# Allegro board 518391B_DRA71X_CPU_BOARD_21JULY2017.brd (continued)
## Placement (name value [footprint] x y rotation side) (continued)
R249  4.7k  [R402-25]  148.84 84.2 270 bottom
R250  1K  [R402-25]  140.97 83.44 180 bottom
R251  10K  [R402-25]  134.75 83.44 180 bottom
R252  0  [R402-25]  42.16 85.47 0 bottom
R253  0  [R402-25]  37.97 85.47 0 bottom
R254  1K  [R402-25]  140.97 81.53 180 bottom
R255  10K  [R402-25]  134.75 81.41 180 bottom
R256  0  [R402-25]  42.16 83.69 0 bottom
R257  0  [R402-25]  37.97 83.69 0 bottom
R258  1K  [R402-25]  140.97 79.5 180 bottom
R259  10K  [R402-25]  134.75 79.5 180 bottom
R261  0  [R402-25]  37.97 81.91 0 bottom
R262  10K  [R402-25]  72.52 77.22 180 bottom
R263  100  [R402-25]  74.3 76.71 270 bottom
R264  22  [R402-25]  76.96 76.33 180 bottom
R265  0  [R201-6P6SPC]  77.85 74.8 0 bottom
R266  0  [R201-6P6SPC]  77.85 73.91 0 bottom
R267  0  [R201-6P6SPC]  79.38 72.52 0 bottom
R268  47K  [R402-25]  129.16 63.88 90 bottom
R269  47K  [R402-25]  122.05 64.9 270 bottom
R270  47K  [R402-25]  129.16 61.85 270 bottom
R271  47K  [R402-25]  119.38 61.98 270 bottom
R272  47K  [R402-25]  126.36 64.77 270 bottom
R273  47K  [R402-25]  119.38 64.9 270 bottom
R274  NP  [R402-25]  145.29 71.37 270 bottom
R275  40.2K  [R402-25]  144.14 71.37 90 bottom
R276  49.9  [SM-7351-RES-0402]  62.36 71.25 90 bottom
R277  49.9  [SM-7351-RES-0402]  61.21 71.25 90 bottom
R278  49.9  [SM-7351-RES-0402]  60.07 71.25 90 bottom
R279  49.9  [SM-7351-RES-0402]  58.93 71.25 90 bottom
R280  49.9  [SM-7351-RES-0402]  57.78 71.25 90 bottom
R281  49.9  [SM-7351-RES-0402]  56.64 71.25 90 bottom
R282  49.9  [SM-7351-RES-0402]  55.5 71.25 90 bottom
R283  49.9  [SM-7351-RES-0402]  54.36 71.25 90 bottom
R284  49.9  [SM-7351-RES-0402]  53.21 71.25 90 bottom
R285  49.9  [SM-7351-RES-0402]  52.07 71.25 90 bottom
R286  49.9  [SM-7351-RES-0402]  50.93 71.25 90 bottom
R287  49.9  [SM-7351-RES-0402]  49.78 71.25 90 bottom
R288  49.9  [SM-7351-RES-0402]  48.64 71.25 90 bottom
R289  47K  [R402-25]  126.36 62.1 270 bottom
R290  10K  [R402-25]  148.08 68.96 180 bottom
R291  47K  [R402-25]  122.05 60.96 90 bottom
R292  22  [R402-25]  98.93 67.06 270 bottom
R293  680  [R402-25]  10.03 63.63 90 bottom
R294  NP-0  [R402-25]  8.76 63.63 90 bottom
R295  47K  [R402-25]  124.08 60.96 270 bottom
R296  1K  [R402-25]  123.44 63.63 90 bottom
R297  NP  [R402-25]  141.48 63.25 270 bottom
R298  40.2K  [R402-25]  140.34 63.25 90 bottom
R299  0  [R402-25]  124.71 59.56 0 bottom
R300  NP  [R402-25]  124.71 58.55 180 bottom
R301  NP-75  [R402-25]  12.57 62.36 90 bottom
R302  NP-75  [R402-25]  15.11 61.09 90 bottom
R303  49.9  [SM-7351-RES-0402]  80.14 60.71 90 bottom
R304  680  [R402-25]  12.57 59.82 90 bottom
R305  0  [R201-6P6SPC]  151.38 58.42 270 bottom
R306  10K  [R402-25]  153.54 57.91 270 bottom
R307  4.7K  [R402-25]  121.92 53.97 90 bottom
R308  100  [R402-25]  127 54.61 270 top
R309  0  [R402-25]  119.38 54.48 90 bottom
R310  4.7K  [R402-25]  118.11 54.48 90 bottom
R311  4.7K  [R402-25]  116.97 54.48 90 bottom
R312  4.7K  [R402-25]  120.65 53.97 270 bottom
R313  10K  [R402-25]  33.53 52.7 180 bottom
R314  680  [R402-25]  10.03 52.2 90 bottom
R315  NP-0  [R402-25]  8.76 52.2 90 bottom
R316  100  [R402-25]  133.22 51.82 90 bottom
R317  100  [R402-25]  132.21 51.82 90 bottom
R318  NP-75  [R402-25]  12.57 50.93 90 bottom
R319  10K  [R402-25]  140.46 49.91 270 bottom
R320  10K  [R402-25]  33.66 49.78 180 bottom
R321  NP-75  [R402-25]  15.11 49.66 90 bottom
R322  10K  [R402-25]  132.97 48.89 0 bottom
R323  1K  [R402-25]  130.81 48.89 0 bottom
R324  100  [R402-25]  41.66 48.39 180 bottom
R325  200  [R402-25]  39.5 48.39 180 bottom
R326  680  [R402-25]  12.57 48.39 90 bottom
R327  100  [R402-25]  128.27 48.13 0 bottom
R328  4.7K  [R402-25]  122.56 48.13 270 bottom
R329  4.7K  [R402-25]  121.28 48.13 270 bottom
R330  4.7K  [R402-25]  120.14 48.13 270 bottom
R331  100  [R402-25]  128.27 47.12 0 bottom
R332  100K  [R402-25]  139.7 46.86 180 bottom
R333  10K  [R402-25]  22.23 46.74 270 bottom
R334  10K  [R402-25]  150.88 46.23 90 bottom
R335  100  [R402-25]  128.27 46.1 0 bottom
R336  100  [R402-25]  158.5 45.97 180 bottom
R337  NP  [R402-25]  156.97 45.47 270 bottom
R338  10K  [R402-25]  155.83 45.47 90 bottom
R339  NP  [R402-25]  154.69 45.47 90 bottom
R340  10K  [R402-25]  153.54 45.47 270 bottom
R341  100  [R402-25]  128.27 45.08 0 bottom
R342  10K  [R402-25]  116.46 44.7 180 bottom
R343  0  [R402-25]  100.08 44.7 180 bottom
R344  1.5K  [R402-25]  119.13 44.58 270 bottom
R345  4.7K  [R402-25]  135.89 44.45 90 bottom
R346  240  [R402-25]  116.46 43.69 180 bottom
R347  10K  [R402-25]  106.81 43.43 180 bottom
R348  10K  [R402-25]  139.83 43.31 0 bottom
R349  100  [R402-25]  135.89 42.29 270 bottom
R350  4.7K  [R402-25]  106.81 42.16 0 bottom
R351  4.7K  [R402-25]  106.81 40.89 0 bottom
R352  680  [R402-25]  10.03 40.77 90 bottom
R353  NP-0  [R402-25]  8.76 40.77 90 bottom
R354  10K  [R402-25]  138.18 40.39 270 bottom
R355  10K  [R402-25]  136.78 40.39 90 bottom
R356  100  [R402-25]  132.72 40.39 90 bottom
R357  100  [R402-25]  131.57 40.39 90 bottom
R358  10K  [R402-25]  117.98 39.75 0 bottom
R359  NP-75  [R402-25]  12.57 39.5 90 bottom
R360  10K  [R402-25]  117.98 38.61 0 bottom
R361  NP-75  [R402-25]  15.11 38.23 90 bottom
R362  0  [R402-25]  158.24 37.97 0 bottom
R363  63.4K  [R402-25]  155.96 37.97 0 bottom
R364  63.4K  [R402-25]  153.8 37.97 0 bottom
R365  10K  [R402-25]  117.98 37.46 0 bottom
R366  680  [R402-25]  12.57 36.96 90 bottom
R367  0  [R402-25]  158.24 36.83 0 bottom
R368  10K  [R402-25]  155.96 36.83 180 bottom
R369  10K  [R402-25]  153.8 36.83 180 bottom
R370  10K  [R402-25]  87.63 40.51 270 bottom
R371  100  [R402-25]  129.03 35.56 270 bottom
R372  100  [R402-25]  127.89 35.56 270 bottom
R373  47K  [R402-25]  86.61 39.75 270 bottom
R374  10K  [R402-25]  113.54 34.42 90 bottom
R375  10K  [R402-25]  112.27 34.42 270 bottom
R376  100  [R402-25]  109.73 34.42 90 bottom
R377  NP  [R402-25]  101.47 34.04 90 bottom
R378  10K  [R402-25]  84.2 39.24 0 bottom
R379  1.5K  [R402-25]  156.97 31.37 90 bottom
R380  1.5K  [R402-25]  155.7 31.37 90 bottom
R381  10K  [R402-25]  158.62 30.86 0 bottom
R382  10K  [R402-25]  136.27 29.84 90 bottom
R383  10K  [R402-25]  128.65 29.84 270 bottom
R384  10K  [R402-25]  158.62 29.72 0 bottom
R385  680  [R402-25]  10.03 29.34 90 bottom
R386  NP-0  [R402-25]  8.76 29.34 90 bottom
R387  NP-75  [R402-25]  12.57 28.07 90 bottom
R388  62  [R1206-40X70]  133.48 27.05 180 bottom
R389  62  [R1206-40X70]  124.59 27.05 0 bottom
R390  NP-75  [R402-25]  15.11 26.8 90 bottom
R391  NP  [R402-25]  101.47 26.42 90 bottom
R392  680  [R402-25]  12.57 25.53 90 bottom
R393  NP  [R402-25]  133.35 25.27 0 bottom
R394  NP  [R402-25]  130.18 25.15 180 bottom
R395  680  [R402-25]  10.03 17.91 90 bottom
R396  NP-0  [R402-25]  8.76 17.91 90 bottom
R397  NP-75  [R402-25]  12.57 16.64 90 bottom
R398  NP-75  [R402-25]  15.11 15.37 90 bottom
R399  680  [R402-25]  12.57 14.1 90 bottom
R401  NP  [R402-25]  75.18 122.68 180 bottom
R402  100  [R402-25]  73.79 79.5 180 bottom
R403  33  [R402-25]  144.4 133.35 0 bottom
R404  33  [R402-25]  144.4 132.21 0 bottom
R405  33  [R402-25]  144.4 130.81 0 bottom
R406  33  [R402-25]  144.4 129.67 0 bottom
R407  33  [R402-25]  144.4 128.27 0 bottom
R408  33  [R402-25]  144.4 127 0 bottom
R409  1K  [R402-25]  160.53 125.09 0 top
R410  10K  [R402-25]  141.86 125.73 0 bottom
R411  33  [R402-25]  144.4 125.73 0 bottom
R412  10K  [R402-25]  160.78 132.46 270 top
R413  1K  [R201-6P6SPC]  134.87 84.45 0 bottom
R414  2.2K  [R402-25]  79.12 147.95 0 bottom
R415  2.2K  [R402-25]  79.25 141.6 0 bottom
R416  10K  [R201-6P6SPC]  80.9 148.84 90 bottom
R417  1K  [R201-6P6SPC]  134.87 78.23 0 bottom
R418  1K  [R201-6P6SPC]  134.87 80.39 0 bottom
R419  1K  [R201-6P6SPC]  134.87 82.42 0 bottom
R420  1K  [R201-6P6SPC]  134.87 86.49 0 bottom
R421  1K  [R201-6P6SPC]  134.87 88.52 0 bottom
R422  1K  [R201-6P6SPC]  70.99 110.49 180 top
R423  10K  [R201-6P6SPC]  139.83 92.33 180 bottom
R424  0  [R201-6P6SPC]  143.13 91.95 270 bottom
R425  10K  [R402-25]  151.76 103.38 270 bottom
R426  100  [R402-25]  135.76 26.29 180 top
R427  100  [R402-25]  122.43 93.98 180 bottom
R428  2K  [R402-25]  77.22 131.32 0 top
R429  0  [R201-6P6SPC]  110.24 94.49 180 bottom
R430  100K  [R402-25]  69.85 115.06 90 bottom
R431  274K  [R402-25]  72.52 119.76 180 bottom
R432  100K  [R402-25]  72.52 117.47 180 bottom
R433  0  [R402-25]  79.63 111.89 270 bottom
RJ1  0  [JMP402-25]  128.65 150.11 270 top
RJ2  1000pF  [JMP402-25]  95.38 136.14 90 top
RJ4  0  [JMP402-25]  162.05 104.14 270 top
RJ5  0.A  [JMP402-25]  116.71 95.38 270 top
RJ6  0  [JMP402-25]  37.34 90.8 0 top
RJ7  0  [JMP402-25]  37.34 89.53 0 top
RJ8  0  [JMP402-25]  37.34 88.27 0 top
RJ9  1000pF  [JMP402-25]  41.15 87.76 90 top
RJ10  0  [JMP402-25]  37.34 86.99 0 top
RJ12  0.A  [JMP402-25]  64.52 37.85 0 top
RJ13  0.A  [JMP402-25]  64.52 30.35 0 top
RJ14  NP  [JMP402-25]  95.38 18.16 270 top
RJ15  1000pF  [JMP402-25]  160.27 12.19 180 top
RJ16  10K.A  [JMP402-25]  138.68 74.04 180 bottom
RJ17  10K.A  [JMP402-25]  138.68 72.77 180 bottom
RJ18  10K.A  [JMP402-25]  133.86 71.63 180 bottom
RJ19  10K.A  [JMP402-25]  133.86 70.36 180 bottom
RJ20  10K.A  [JMP402-25]  133.86 69.09 180 bottom
RJ21  10K.A  [JMP402-25]  133.86 67.82 180 bottom
RJ22  10K.A  [JMP402-25]  133.86 66.55 180 bottom
RJ23  10K.A  [JMP402-25]  133.86 65.28 180 bottom
RJ24  10K.A  [JMP402-25]  136.02 62.36 180 bottom
RJ25  10K.A  [JMP402-25]  136.02 61.09 180 bottom
RJ26  0.A  [JMP402-25]  119.76 50.8 90 bottom
RJ27  0.B  [JMP402-25]  131.95 35.94 180 bottom
RJ28  0.B  [JMP402-25]  131.95 34.8 180 bottom
RJ29  0  [JMP402-25]  43.18 80.14 180 bottom
RJ30  0.A  [JMP402-25]  81.79 23.49 180 top
RJ31  0.B  [JMP402-25]  136.78 27.43 180 top
RU1  SN74CBTLV3257PW  [TSSOP16-14X70]  149.73 109.35 180 bottom
RU2  SN74CBTLV3257PW  [TSSOP16-14X70]  143.13 109.35 180 bottom
SW1  TDA06H0SB1R  [SW6-30X50-TDA]  137.79 84.45 90 top
SW2  SW DIP-2  [SW2-30X50-TDA]  76.96 111.12 90 top
TP1  TP  [TP-30RD13]  22.86 160.27 0 top
TP2  TP  [TP-30RD13]  83.95 150.5 90 top
TP3  TP  [TP-30RD13]  122.43 145.92 0 top
TP4  TP  [TP-30RD13]  152.53 142.37 0 top
TP5  TP  [TP-30RD13]  44.45 140.46 90 top
TP6  TP  [TP-30RD13]  95.63 139.19 90 top
TP7  TP  [TP-30RD13]  65.79 134.24 0 top
TP8  TP  [TP20]  145.8 123.19 270 top
TP9  TP  [TP-30RD13]  58.55 122.3 90 top
TP10  TP  [TP-30RD13]  104.39 120.14 180 top
TP11  TP  [TP20]  133.86 114.3 270 top
TP12  TP  [TP-30RD13]  76.2 116.71 90 top
TP13  SMT-TP  [TP1-70X135]  58.8 106.93 90 top
TP14  TP  [TP-30RD13]  63.5 111.51 90 top
TP15  TP  [TP-30RD13]  43.56 108.71 0 top
TP16  SMT-TP  [TP1-70X135]  21.46 108.2 0 top
TP17  SMT-TP  [TP1-70X135]  127.38 107.06 0 top
TP18  TP  [TP-30RD13]  33.4 98.55 90 top
TP19  TP  [TP20]  151.76 100.84 270 top
TP20  TP  [TP-30RD13]  125.48 92.96 0 top
TP21  TP  [TP-30RD13]  153.03 95.63 90 top
TP22  TP  [TP-30RD13]  125.48 94.74 0 top
TP23  TP  [TP-30RD13]  126.62 95.63 0 top
TP24  TP  [TP-30RD13]  119 90.3 0 top
TP29  TP  [TP20]  166.62 79.63 180 top
TP31  TP  [TP-30RD13]  117.73 80.52 0 top
TP32  TP  [TP-30RD13]  77.09 72.52 0 top
TP34  TP  [TP20]  89.66 64.39 90 top
TP35  TP  [TP20]  88.27 63.88 90 top
TP36  TP  [TP-30RD13]  74.55 63.25 0 top
TP37  TP  [TP20]  89.66 63.12 90 top
TP38  TP  [TP-30RD13]  160.4 57.02 0 top
TP39  SMT-TP  [TP1-70X135]  137.16 56.52 0 top
TP40  TP  [TP-30RD13]  74.8 51.82 90 top
TP41  TP  [TP-30RD13]  74.8 50.04 0 top
TP42  TP  [TP-30RD13]  67.06 44.96 0 top
TP43  TP  [TP-30RD13]  157.48 42.29 0 top
TP44  TP  [TP-30RD13]  158.88 42.29 0 top
TP45  TP  [TP-30RD13]  153.42 39.75 0 top
TP46  TP  [TP-30RD13]  154.94 39.75 0 top
TP47  TP  [TP-30RD13]  142.49 39.24 0 top
TP48  TP  [TP20]  111 36.45 0 top
TP49  TP  [TP-30RD13]  122.56 35.18 180 top
TP50  TP  [TP-30RD13]  83.69 40.39 90 top
TP51  TP  [TP-30RD13]  84.33 32.51 90 top
TP52  TP  [TP-30RD13]  64.01 32.26 0 top
TP53  TP  [TP20]  115.57 28.96 0 top
TP54  TP  [TP-30RD13]  147.57 26.54 0 top
TP55  TP  [TP-30RD13]  151.26 26.29 0 top
TP56  TP  [TP-30RD13]  64.01 24.76 0 top
TP57  TP  [TP-30RD13]  94.49 24.64 0 top
TP58  TP  [TP-30RD13]  139.95 24.64 0 top
TP59  TP  [TP-30RD13]  91.57 15.37 0 top
TP60  SMT-TP  [TP1-70X135]  64.01 20.7 0 top
TP61  TP  [TP-30RD13]  85.6 21.46 180 top
TP62  TP  [TP-30RD13]  146.3 12.7 0 top
TP63  SMT-TP  [TP1-70X135]  34.04 119.89 180 bottom
TP64  SMT-TP  [TP1-70X135]  140.59 146.69 180 bottom
TP65  SMT-TP  [TP1-70X135]  128.27 54.86 180 bottom
TP66  SMT-TP  [TP1-70X135]  60.2 24 180 bottom
TP67  TP  [TP-30RD13]  126.62 93.85 0 top
TP68  <value>  [TP-20RD10]  31.5 62.23 0 top
TP69  <value>  [TP-20RD10]  32.51 61.47 0 top
TP70  <value>  [TP-20RD10]  24.38 56.9 0 top
TP71  <value>  [TP-20RD10]  25.27 56.9 0 top
TP72  <value>  [TP-20RD10]  51.05 64.52 0 top
TP73  <value>  [TP-20RD10]  44.83 61.21 0 top
U1  APPLE_I2C_CHIP - NOPOP  [IC8-CP-USON]  85.6 163.19 180 bottom
U2  tpd4e05u06-q1  [DQA-PSON10]  131.83 155.45 0 top
U3  TPD1E05U06  [DPY-RDPADS]  97.66 155.32 135 top
U4  TPD1E05U06  [DPY-RDPADS]  99.44 155.32 45 top
U5  TPD1E05U06  [DPY-RDPADS]  107.82 155.32 135 top
U6  TPD1E05U06  [DPY-RDPADS]  109.6 155.32 45 top
U7  TPD1E05U06  [DPY-RDPADS]  100.71 153.42 135 top
U8  TPD1E05U06  [DPY-RDPADS]  102.49 153.42 45 top
U9  TPD1E05U06  [DPY-RDPADS]  104.78 153.42 135 top
U10  TPD1E05U06  [DPY-RDPADS]  106.55 153.42 45 top
U11  TPS254900-Q1  [RVC20]  124.97 148.72 0 top
U12  TPD3S716-Q1  [SSOP-16]  154.94 148.08 180 top
U13  SN74LVC1G04DCK  [DCK-5]  147.07 146.81 180 top
U14  SN74LVC1G04DCK  [DCK-5]  150.11 146.81 180 top
U15  LM53603-Q1  [PWP16-14X70-PAD]  91.69 142.24 0 top
U16  LM74610  [DGK8-14X70]  19.43 132.46 270 top
U17  TPD12S016RKTR  [RKT24]  115.57 154.94 270 top
U18  LM5141-Q1  [RGE24-11X28-4MM]  79.38 124.97 90 top
U19  LM5175-Q1  [PWP28-14X70]  52.96 116.97 0 top
U20  TPS22965-Q1DSG  [DSG8-11X20]  103.38 116.97 270 top
U21  LBEN6ZZZHC  [WIFIBTMOD68]  148.34 111.76 180 top
U22  24WC256  [SO8-25X75-295]  39.37 99.19 90 top
U23  MT41K512M16HA-125 AIT:A  [BGA6X16-P8-RE-PKG]  58.55 95 270 top
U24  74AVC4T245QRGYRQ1  [RGY16-12X34]  121.03 94.74 270 top
U25  -  [NEO-M8U]  161.16 89.79 90 top
U26  PCA9306/PCA9306-Q1  [DCU8-10X50]  148.84 85.47 180 top
U27  X777AJGCBD  [J6ENTRY_DRA71X_ZDN_V4]  92.96 84.71 180 top
U28  TAS6424QDKQRQ1  [DKQ56]  28.19 84.71 90 top
U29  MT41K512M16HA-125 AIT:A  [BGA6X16-P8-RE-PKG]  58.55 80.77 270 top
U30  DS90UB921-Q1  [RHS48-11X34]  140.59 66.29 0 top
U31  MTFC32GAKAEDQ-AIT  [BGA100_1MM]  124.21 65.91 0 top
U32  O919A1xxTRGZRQ1  [RGZ48-11X34]  85.22 56.13 180 top
U33  DS90UB934-Q1  [RGZ48-11X34]  152.4 52.07 180 top
U34  Si4790x  [RGZ48-11X34]  47.62 51.05 0 top
U35  TPS51200DRC  [DRC10-11X33]  62.86 49.66 180 top
U36  Si4791x/2x  [QFN84-12X12]  28.07 49.28 90 top
U37  NP-R7F7010403AFP  [PM64-12X70]  133.99 46.1 0 top
U38  24WC256  [SO8-25X75-295]  103.25 42.8 270 top
U39  TPS22965-Q1DSG  [DSG8-11X20]  68.96 42.04 0 top
U40  DP83TC811-Q1  [RND36-24X10]  120.4 40.39 270 top
U41  TPS7A8101-Q1  [DRB8-14X33]  73.41 34.92 270 top
U42  TPS61252  [DSG8-11X20]  89.66 34.54 270 top
U43  TPS1H100-Q1  [PWP14-14X70-PAD]  145.03 34.42 180 top
U44  TPS7B7702-Q1  [PWP16-14X70-PAD]  155.7 34.42 0 top
U45  TCAN1042HGVQ1  [SO8-25X75]  134.37 32.77 180 top
U46  TCAN1042HGVQ1  [SO8-25X75]  126.75 32.77 180 top
U47  SN65HVDA100-Q1  [SO8-25X75]  111.63 31.75 180 top
U48  TPS22965-Q1DSG  [DSG8-11X20]  92.58 27.56 180 top
U49  TPS7A8101-Q1  [DRB8-14X33]  73.41 27.43 270 top
U50  LMR23625CF-Q1  [DDA8-PAD]  157.61 17.4 270 top
U51  TPS1H100-Q1  [PWP14-14X70-PAD]  142.49 16.64 0 top
U52  FT232RQ  [QFN32_5X5]  16.76 101.98 180 bottom
U53  TPD1E10B09  [DPY]  7.49 63.63 270 bottom
U54  SN74LVC1G125DCKR  [DCK-5]  115.95 62.48 0 bottom
U55  74LVC125APWR  [PW14-12X70]  45.85 61.85 90 bottom
U56  74LVC125APWR  [PW14-12X70]  25.53 61.21 90 bottom
U57  TPD1E10B09  [DPY]  11.3 59.82 90 bottom
U58  TPD1E10B09  [DPY]  7.49 52.2 270 bottom
U59  TPD1E10B09  [DPY]  11.3 48.39 90 bottom
U60  TPD1E10B09  [DPY]  7.49 40.77 270 bottom
U61  TPD1E10B09  [DPY]  11.3 36.96 90 bottom
U62  TPD1E10B09  [DPY]  7.49 29.34 270 bottom
U63  TPD1E10B09  [DPY]  11.3 25.53 90 bottom
U64  TPD1E10B09  [DPY]  7.49 17.91 270 bottom
U65  TPD1E10B09  [DPY]  11.3 14.1 90 bottom
U66  TPD2E001DRL-Q1  [DRL5-12X40]  147.57 127.76 270 bottom
U67  TPD2E001DRL-Q1  [DRL5-12X40]  147.57 130.3 270 bottom
U68  TPD2E001DRL-Q1  [DRL5-12X40]  147.57 132.84 270 bottom
U69  TPD2E001DRL-Q1  [DRL5-12X40]  147.57 125.22 270 bottom
U70  TPS22965DSG  [DSG8-11X20]  157.35 130.94 90 top
U71  74CBTLV1G125CRG4  [DCK-5]  78.61 150.24 180 bottom
U72  74CBTLV1G125CRG4  [DCK-5]  78.74 143.76 180 bottom
U73  TPD4E002  [DRL5-12X40]  94.23 158.37 0 bottom
U74  INA226AIDGSR  [DGS10-11X60]  30.48 140.84 270 bottom
U75  SN74LVC1G125DCKR  [DCK-5]  116.08 91.44 180 top
U76  NP-TPS3803-01-Q1  [DCK-5]  77.6 111.89 0 bottom
X1  8MHz - 8pF  [XTAL150SMD_125X196]  145.29 45.59 90 top
X2  36.864MHz  [XTAL4-55X47-3225]  22.1 42.42 0 bottom
Y1  KC2520M32K7680CM3E00  [OSC-KC2520]  133.6 111.38 0 top
Y2  25MHz/10pF  [XTAL4-ABM11]  114.3 40.64 180 top
Y3  19.2MHz/10pF  [XTAL4-ABM11]  94.11 98.17 270 bottom

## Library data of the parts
ANT1 = TE-2118016-1: Tolerance: X; User Part Number: X
C1-C3 C23 C58 C65 C538 = CAP
C4 C6 C7 C16 C39 C47 C50 C67 C87 C93 C97 C107 C110 C117 C143 C144 C153 C154 C156 C163 C266 C317 C330 C360 C371 C376 C381 C384 C397 C400 = CAP NP: Tolerance: X; User Part Number: X
C5 C9 C11 C15 C17 C29-C35 C37 C38 C42 C86 C88 C92 C101 C105 C111 C135 C177 C191 C214 C225-C227 C231 C247 C248 C250 C253 C339 C355 C366 C389 C399 C405 C468 = CAP NP_0: Tolerance: X; User Part Number: X
C8 C12 C20-C22 C24-C26 C116 C122 C123 C127 C129 C131-C134 C145 C146 C167 C172 C173 C181 C189 C212 C239 C242 C249 C256 C427 C435 C436 C485 C541 C546 C547 C552 = CAP: Tolerance: X; User Part Number: X
C10 C41 C48 C51 C54 C66 C70 C71 C73 C81 C83 C157 C160 C161 C260-C262 C267-C271 C439 C442 C448 C476 C478 C489 C500 C504 C505 C512 C523 C529 C532 C534 C548 C549 = CAP NP: User Part Number: USERPART#; Tolerance: TOLERANCE
C13 C14 C36 C43 C53 C554 = CAP NP_2: User Part Number: USERPART#; Tolerance: TOLERANCE
C18 C19 C263 C433 C539 C540 C542-C545 = Cap 100nF Cermc 16V 10% 603_4: User Part Number: USERPART#; Tolerance: TOLERANCE
C27 C49 C76 C168 C257 C277 C282 C283 C285 C287 C288 C290 C291 C296 C342 C353 C379 C390 C430-C432 C550 = CAP_AM_0402_0.1uf_x7r_16v_10%_X: User Part Number: USERPART#; Tolerance: TOLERANCE
C28 = CAP_AM_0402_0.1uf_x7r_16v_10%_X: Tolerance: X; User Part Number: X
C40 C61 C79 C175 C182-C185 C187 C192 C195 C196 C199-C202 C210 C213 C216 C217 C219 C224 C240 C244 C265 C276 C292 C375 C498 C503 C506 C553 = CAP NP_3: User Part Number: USERPART#; Tolerance: TOLERANCE
C44 C119 C128 C190 C450 C464 C469 C475 = CAP_AM_0805_4.7uf_x7r_16v_10_X: Tolerance: X; User Part Number: X
C45 C78 = CAP NP_2: Tolerance: X; User Part Number: X
C55 C62 C174 C245 = CAP_0402_220pf_x7r_50v_10%_X_SD: User Part Number: USERPART#; Tolerance: +/-10%; tolerance: +/-10%
C56 C59 C64 = CAP NP_0: Tolerance: 20%; User Part Number: X; tolerance: 20%
C57 C176 C238 C516 C517 C524 C527 = CAP_0402_0.1uf_x7r_16v_10%_X_SD: User Part Number: USERPART#; Tolerance: +/-10%; tolerance: +/-10%
C60 C188 C222 = CAP_0402_1uF_X7R_6.3V_10%_X_SD: Tolerance: 10%; User Part Number: X; tolerance: 10%
C63 C68 C69 C72 C74 C75 C142 C159 C162 C171 C220 C228 C234 C258 C259 C409 C410 C429 C445 C454 C462 C466 C471 C472 C479 C480 C482 C484 C486-C488 C491-C493 C496 C497 C499 C507-C511 C514 C515 C518 C519 C521 C522 C525 C526 C528 C533 = CAP: User Part Number: USERPART#; Tolerance: TOLERANCE
C77 = CAP_AM_0603_1.0uf_x7r_16v_10_X: Tolerance: X; User Part Number: X
C80 C82 C84 C91 C96 C272-C274 C293-C295 C297 C299 C311-C315 C319 C321 C325-C328 C332 C341 C347 C348 C351 C352 C354 C357 C361 C362 C364 C367 C368 C377 C386 C391 C392 C413-C415 C417-C425 = CAP_AM_0402_0.47uf_x7s_10v_20_X: Tolerance: +/-10%; User Part Number: USERPART#; tolerance: +/-10%
C85 C90 C102 C106 C155 C158 C164 C346 C365 C398 C404 = CAP NP: Tolerance: TOLERANCE; User Part Number: USERPART#
C89 C98 C108 C120 C194 C203-C205 C207 C208 C235 C237 C241 C281 C307 C447 C474 C536 C537 C551 = CAP_AM_0805_10uf_x7r_10v_10_X: Tolerance: X; User Part Number: X
C94 C95 C99 C100 C103 C104 C109 C209 C223 C243 C252 C438 C449 C473 C490 C502 C513 C520 C530 C531 C535 = CAP NP_3: Tolerance: X; User Part Number: X
C112 C113 C115 C121 C350 = CAP NP_0: Tolerance: TOLERANCE; User Part Number: USERPART#
C114 C370 C428 = CAP_AM_0402_0.47uf_x7s_10v_20_X: User Part Number: USERPART#; Tolerance: +/-10%; tolerance: +/-10%
C118 C284 C434 = CAP_AM_0402_1uF_X7S_10V_10%_X: User Part Number: USERPART#; Tolerance: 10%; tolerance: 10%
C124 C125 = CAP: User Part Number: USERPART#; Tolerance: TOLERANCE; signal model: CAP_C402-25_0.1UF
C126 C130 C165 C166 = CAP_AM_1210_47uf_x7r_6.3v_20_X: Tolerance: X; User Part Number: X
C136 C138 C141 C147 C149 C151 C169 C180 C197 C198 C211 C215 C221 C229 C230 C251 C254 C495 = CAP NP_3: Tolerance: TOLERANCE; User Part Number: USERPART#
C137 C139 C140 C148 C150 C152 C170 C179 = CAP_AM_0603_2.2uf_x7r_6.3v_10_X: Tolerance: TOLERANCE; User Part Number: USERPART#
C178 C278-C280 C298 C300 C304-C306 C308-C310 C318 C331 C333 C335-C338 C340 C345 C349 C356 C359 C369 C378 C382 C383 C416 C446 C455-C457 C467 C481 = CAP_AM_0402_0.1uf_x7r_16v_10%_X: Tolerance: TOLERANCE; User Part Number: USERPART#
C186 C451-C453 C459-C461 C494 C501 = CAP_AM_0603_1.0uf_x7r_16v_10_X: User Part Number: USERPART#; Tolerance: TOLERANCE
C206 C218 C236 C246 C255 = CAP_AM_0603_0.47uf_x7r_16v_10_X: Tolerance: X; User Part Number: X
C232 C233 = CAP NP: Tolerance: X; User Part Number: X; signal model: CAP_NP_C603-35X45_0.1UF
C264 = CAP NP_0: User Part Number: USERPART#; Tolerance: TOLERANCE
C275 = CAP .1 uF 10% 0603: User Part Number: USERPART#; Tolerance: TOLERANCE
C286 C301 C302 C320 C322 C324 C329 C334 C343 C358 C372 C374 C388 C394 C395 C406-C408 C412 C426 = CAP_AM_0402_1uF_X7S_10V_10%_X: Tolerance: 10%; User Part Number: USERPART#; tolerance: 10%
C289 C303 C323 C344 C373 C380 C385 C393 C401-C403 = CAP_AM_0508_1uF_X7S_4V_20%_X: tolerance: 20%
C316 C363 C387 C396 = CAP NP_0: User Part Number: X; Tolerance: X
C411 C437 = Cap 100nF Cermc 16V 10% 603_4: Tolerance: X; User Part Number: X
C440 C441 C443 C444 C458 C463 C465 C470 C477 = CAP_AM_0603_2.2uf_x7r_6.3v_10_X: Tolerance: X; User Part Number: X
C483 = CAP_AM_0603_1.0uf_x7r_16v_10_X: Tolerance: TOLERANCE; User Part Number: USERPART#
D1 D2 D4 D24 = DIODE ZENER: Tolerance: TOLERANCE; User Part Number: USERPART#
D3 = PDS5100
D5 D7 D9 = DIODE SCHOTTKY_0: Tolerance: TOLERANCE; User Part Number: USERPART#
D6 D8 = DIODE
D10 D11 D20 = LED_0: Tolerance: X; User Part Number: X
D12 D13 = DIODE BI-DIR TRIG_0: Tolerance: X; User Part Number: X
D14 D17 = DIODE BI-DIR TRIG_0: Tolerance: TOLERANCE; User Part Number: USERPART#
D15 D18 = CM1213A-01SO: Tolerance: X; User Part Number: X
D16 D19 = DIODE: Tolerance: X; User Part Number: X
D21 D22 = Diode_SMCJ15CA
D23 = DIODE SCHOTTKY_0: User Part Number: X; Tolerance: X
DPX1 = DPX205950DT-9008A1
DS1 = LED_RED_0: Tolerance: X; User Part Number: X
E1-E7 = EMIFIL_0805_0.47uF_2A_80dB27M_X: Tolerance: TOL; User Part Number: PART#
FB1 FB2 L16 L17 L19 L20 L24 L36 L51 L52 L59-L63 = FERRITE CHIP_0: Tolerance: X; User Part Number: X
FL1 = DLW21SN121HQ2: User Part Number: PART#; Tolerance: TOL; signal model: DLW21SN121HQ2_EMI-36X15-DLW21_D
FL2 FL5 FL6 = DLW21SN121HQ2: User Part Number: PART#; Tolerance: TOL
FL3 FL4 FL7-FL9 = DLW21SN900HQ2: User Part Number: PART#; Tolerance: TOL; signal model: DLW21SN900HQ2_EMI-36X15-DLW21-R
J1 J2 = 1932258-1-USB3
J3 = HEADER 5X2: Tolerance: X; User Part Number: X
J4 = 4 HEADER: User Part Number: X; Tolerance: X
J6 J16 J18 P5 = 59S20X-400L5-Z: Tolerance: TOLERANCE; User Part Number: USERPART#
J7 = USBMINI_B_0
J8 = HEADER 6X2: Tolerance: X; User Part Number: X
J9 = CONN TRBLK 8: User Part Number: X; Tolerance: X
J10 J13 = HEADER 2: Tolerance: X; User Part Number: X
J11 J12 = HEADER 3: Tolerance: TOL; User Part Number: PART#
J14 = MIPI-QTH-030_1: User Part Number: PART#; Tolerance: TOL
J15 = HEADER 7X2: User Part Number: X; Tolerance: X
J17 = Molex34826-0124: Tolerance: TOLERANCE; User Part Number: USERPART#
J19 = FX8-120P-SV1-91
J20 = HEADER 5: User Part Number: X; Tolerance: X
J21 = HEADER 40_0
J22 = PWR_JACK_0
L1 = CHOKE HASH-IRON: Tolerance: TOLERANCE; User Part Number: USERPART#
L2 = INDUCTOR IRON
L3 = INDUCTOR IRON: Tolerance: TOLERANCE; User Part Number: USERPART#
L4 = CHOKE HASH-IRON: Tolerance: X; User Part Number: X
L5 = CHOKE HASH-IRON: User Part Number: USERPART#; Tolerance: TOLERANCE
L6 L34 = INDUCTOR IRON: Tolerance: X; User Part Number: X
L7 L8 L10 L11 = INDUCTOR: User Part Number: USERPART#; Tolerance: TOLERANCE
L9 = INDUCTOR_3: Tolerance: X; User Part Number: X
L12-L15 L55-L58 = INDUCTOR IRON: User Part Number: USERPART#; Tolerance: TOLERANCE
L18 L21-L23 = IND_1.47uH_DFE252012C_R47N: User Part Number: USERPART#; Tolerance: TOLERANCE
L25 L26 L28-L31 L33 L35 L37 L39 L42 L43 L45 L46 L48-L50 L53 = INDUCTOR: Tolerance: X; User Part Number: X
L27 = CHOKE: Tolerance: X; User Part Number: X
L32 L38 L41 L47 = INDUCTOR: User Part Number: X; Tolerance: X
L40 = CHOKE: Tolerance: TOLERANCE; User Part Number: USERPART#
L44 = CHOKE CM_AE2002: User Part Number: USERPART#; Tolerance: TOLERANCE; signal model: CHOKE_CM_AE2002_CHOKE4-AE2002_A
L54 = INDUCTOR IRON: User Part Number: X; Tolerance: X
M1-M6 = MHP125-250
M9-M13 = MHP93-200
P1 = HDMI-RA-19_0: Tolerance: TOL; User Part Number: PART#
P2 = D4S20D-40ML5-Y
P3 P4 P6-P8 = Kycon ST-3500_3
P9 = QSH-020-01-L-D-DP-A: Tolerance: TOL; User Part Number: PART#
P10 = MM_CARD_0: User Part Number: X; Tolerance: X
Q1 Q2 Q11 Q12 = BSS138PS: User Part Number: X; Tolerance: X
Q3 = MOSFET_CSD16406Q3_0: User Part Number: X; Tolerance: X
Q4-Q7 Q9 Q10 = BSZ042N06NS: User Part Number: X; Tolerance: X
Q8 = NX3008CBKS: User Part Number: X; Tolerance: X
R1-R7 R11 R13 R17 R18 R23-R26 R29 R33 R36 R39 R40 R51 R57 R58 R60-R63 R65 R67-R70 R104 R105 R117 R118 R120 R122 R128-R133 R135 R137 R138 R140-R145 R150 R153 R154 R157 R163-R171 R173 R174 R177-R182 R184-R193 R198 R199 R203-R207 R209-R212 R215-R218 R221-R224 R232-R234 R237 R238 R252 R253 R256 R257 R261-R264 R274 R275 R290 R292-R294 R296-R298 R301 R302 R304 R306-R319 R321-R323 R326-R332 R334-R361 R363 R365-R368 R371 R372 R374-R377 R379 R382 R383 R385-R387 R390-R392 R395-R399 R401 R402 R414 R415 R426-R428 R430-R432 = R: User Part Number: USERPART#; Tolerance: TOLERANCE
R8-R10 R14-R16 R20-R22 R34 R35 R37 R38 R42 R43 R45 R47 R48 R50 R53 R54 R59 R146-R148 R159-R161 R202 R208 R213 R214 R219 R220 R393 R394 R433 = R_2: User Part Number: USERPART#; Tolerance: TOLERANCE
R12 = RESISTOR: Tolerance: X; User Part Number: X
R19 R225 = R_2: Tolerance: X; User Part Number: X
R27 R28 R30-R32 R72 R74 R75 R77-R82 R97 R98 R100 R102 R103 R126 R136 R139 R155 R156 R162 R239 R242 R265-R267 R320 R324 R325 R362 R364 R369 R380 R381 R384 R416 R423 R424 R429 = R: Tolerance: TOLERANCE; User Part Number: USERPART#
R41 R71 R106 R112 R115 R127 R236 R370 R373 R378 = RES_0402_10k_1.0%_0.063W_X: User Part Number: USERPART#; Tolerance: 1.0%; tolerance: 1.0%
R44 R46 R49 = R_2: User Part Number: X; Tolerance: X
R52 R55 R56 R64 R76 R114 = R_0: User Part Number: USERPART#; Tolerance: TOLERANCE
R66 R73 R99 = R: Tolerance: TOLERANCE; User Part Number: USERPART#; signal model: R_R201-6P6SPC_0
R83-R96 R276-R288 = RES_0402_49.9_1%_0.063W_X: User Part Number: USERPART#; Tolerance: 1.0%; tolerance: 1.0%
R101 = R0402-22: Tolerance: TOLERANCE; User Part Number: USERPART#; signal model: R201-6P6SPC_0a
R107 = R_10K_0402_1%_Multi: Tolerance: TOLERANCE; User Part Number: USERPART#
R110 R183 R305 = R0402-22: Tolerance: TOLERANCE; User Part Number: USERPART#; signal model: R201-6P6SPC_0
R149 R158 R235 R240 R241 R243 R244 R247 R248 R250 R251 R254 R255 R258 R259 = R_1: User Part Number: USERPART#; Tolerance: TOLERANCE
R151 R152 R388 R389 = R: Tolerance: X; User Part Number: X
R172 R175 R176 R194-R197 R200 R201 R226-R231 R268-R273 R289 R291 R295 R300 R403-R412 R425 = RESISTOR: User Part Number: USERPART#; Tolerance: TOLERANCE
R245 R246 R249 = RESISTOR_0: User Part Number: USERPART#; Tolerance: TOLERANCE
R299 = RESISTOR: User Part Number: USERPART#; Tolerance: TOLERANCE; signal model: RESISTOR_R402-25_0
R303 = RES_0402_49.9_1%_0.063W_X: Tolerance: 1.0%; User Part Number: USERPART#; tolerance: 1.0%
R333 = RESISTOR: Tolerance: TOLERANCE; User Part Number: USERPART#
R413 R417-R422 = R_1: Tolerance: TOLERANCE; User Part Number: USERPART#
RJ1 RJ4 RJ6-RJ8 RJ10 RJ29 = RJUMP3A: Tolerance: TOLERANCE; User Part Number: USERPART#
RJ2 RJ5 RJ9 RJ12-RJ26 RJ30 = RJUMP3: Tolerance: TOLERANCE; User Part Number: USERPART#
RJ27 RJ28 RJ31 = RJUMP3B: Tolerance: TOLERANCE; User Part Number: USERPART#
RU1 RU2 = SN74CBT3257PW: Tolerance: X; User Part Number: X
SW1 = SW DIP-6/SM_0: Tolerance: X; User Part Number: X
SW2 = SW DIP-2_0: User Part Number: X; Tolerance: X
TP1-TP7 TP9 TP10 TP12 TP14 TP15 TP18 TP20-TP24 TP31 TP32 TP36 TP38 TP40-TP47 TP50-TP52 TP54-TP59 TP61 TP62 TP67 = TP-30RD13: Tolerance: TOLERANCE; User Part Number: USERPART#
TP8 TP11 TP19 TP29 = TESTPOINT: User Part Number: USERPART#; Tolerance: TOLERANCE
TP13 TP16 TP17 TP39 TP60 TP63-TP66 = SMT-TP
TP34 TP35 TP37 = TP-20: User Part Number: USERPART#; Tolerance: TOLERANCE
TP48 TP53 = TestPoint1_0: User Part Number: USERPART#; Tolerance: TOLERANCE
TP49 = TESTPOINT: Tolerance: TOLERANCE; User Part Number: USERPART#
TP68-TP73 = TP-20RD10
U1 = APPLE_I2C_CHIP: User Part Number: X; Tolerance: X
U2 = tpd4e05u06-q1: Tolerance: TOL; User Part Number: PART#
U3-U10 = TPD1E05U06: Tolerance: X; User Part Number: X
U11 = TPS254900-Q1
U12 = TPD3S716-Q1: User Part Number: USERPART#; Tolerance: TOLERANCE
U13 U14 = SN74LVC1GU04_1: Tolerance: TOL; User Part Number: PART#
U15 = LM53603-Q1: Tolerance: X; User Part Number: X
U16 = LM74610: User Part Number: X; Tolerance: X
U17 = TPD12S016RKTR_QFN24_3: Tolerance: X; User Part Number: X
U18 = LM5141-Q1
U19 = LM5175-Q1: Tolerance: X; User Part Number: X
U20 U39 U48 = IC_TPS22965Q1DSG_SON8_X: User Part Number: X; Tolerance: X
U21 = LBEN6ZZZHC
U22 U38 = 24WC256: User Part Number: X; Tolerance: X
U23 U29 = IC_MT41K128M16JT_DDR3L_96FBGA_X
U24 = 74AVC4T245QRGYRQ1: Tolerance: X; User Part Number: X
U25 = NEO-M8U: Tolerance: X; User Part Number: X
U26 = PCA9306
U27 = IC_J6Entry_17mm_538BGA_v1.1
U28 = TAS6424QDKQRQ1_J6ELR
U30 = DS90UB921Q
U31 = MTFC32GAKAEDQ-AIT: Tolerance: TOL; User Part Number: PART#
U32 = IC_O919A1xxTRGZRQ1_VQFN48_X
U33 = DS90UB934Q
U34 = Si4790x
U35 = IC_TPS51200DRC_SON10_X: User Part Number: X; Tolerance: X
U36 = Si4791x/2x
U37 = R7F701
U40 = DP83TC811-Q1
U41 U49 = TPS7A8101-Q1: Tolerance: X; User Part Number: X
U42 = TPS61252: User Part Number: X; Tolerance: X
U43 U51 = tps1h100-q1: Tolerance: X; User Part Number: X
U44 = TPS7B7702-Q1: Tolerance: X; User Part Number: X
U45 U46 = SN65HVDA541: Tolerance: X; User Part Number: X
U47 = SN65HVDA100-Q1: Tolerance: X; User Part Number: X
U50 = LMR23625CF-Q1: Tolerance: X; User Part Number: X
U52 = FT232RQ_7: User Part Number: PART#; Tolerance: TOL
U53 U57-U65 = TPD1E10B09: Tolerance: X; User Part Number: X
U54 U71 U72 U75 = SN74LVC1G125_0: Tolerance: TOL; User Part Number: PART#
U55 U56 = 74LVC125APWR: User Part Number: USERPART#; Tolerance: TOLERANCE
U66-U69 = TPDE0001RSE_0: Tolerance: TOL; User Part Number: PART#
U70 = TPS22965DSG: User Part Number: X; Tolerance: X
U73 = TPD4E002: Tolerance: TOL; User Part Number: PART#
U74 = INA220IDCN_2: User Part Number: PART#; Tolerance: TOL
U76 = TPS3803-01-Q1: Tolerance: TOL; User Part Number: PART#
X1 = CRYSTAL
X2 Y2 Y3 = CRYSTAL 4-PIN_0
Y1 = OSC4/SM_0: User Part Number: X; Tolerance: X

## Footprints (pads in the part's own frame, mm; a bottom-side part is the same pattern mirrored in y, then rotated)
ANT-2118016
  rect 1.397x1.397 smd: 1(5.486,-4.521) 2(12.675,-4.521)
  rect 1.524x1.016 smd: 3(0.762,-0.508) 4(17.272,-0.508)
BGA6X16-P8-RE-PKG
  round 0.351 smd: A1(-3.2,6) A2(-2.4,6) A3(-1.6,6) A7(1.6,6) A8(2.4,6) A9(3.2,6) B1(-3.2,5.2) B2(-2.4,5.2) B3(-1.6,5.2) B7(1.6,5.2) B8(2.4,5.2) B9(3.2,5.2) C1(-3.2,4.4) C2(-2.4,4.4) C3(-1.6,4.4) C7(1.6,4.4) C8(2.4,4.4) C9(3.2,4.4) D1(-3.2,3.6) D2(-2.4,3.6) D3(-1.6,3.6) D7(1.6,3.6) D8(2.4,3.6) D9(3.2,3.6) E1(-3.2,2.8) E2(-2.4,2.8) E3(-1.6,2.8) E7(1.6,2.8) E8(2.4,2.8) E9(3.2,2.8) F1(-3.2,2) F2(-2.4,2) F3(-1.6,2) F7(1.6,2) F8(2.4,2) F9(3.2,2) G1(-3.2,1.2) G2(-2.4,1.2) G3(-1.6,1.2) G7(1.6,1.2) G8(2.4,1.2) G9(3.2,1.2) H1(-3.2,0.4) H2(-2.4,0.4) H3(-1.6,0.4) H7(1.6,0.4) H8(2.4,0.4) H9(3.2,0.4) J1(-3.2,-0.4) J2(-2.4,-0.4) J3(-1.6,-0.4) J7(1.6,-0.4) J8(2.4,-0.4) J9(3.2,-0.4) K1(-3.2,-1.2) K2(-2.4,-1.2) K3(-1.6,-1.2) K7(1.6,-1.2) K8(2.4,-1.2) K9(3.2,-1.2) L1(-3.2,-2) L2(-2.4,-2) L3(-1.6,-2) L7(1.6,-2) L8(2.4,-2) L9(3.2,-2) M1(-3.2,-2.8) M2(-2.4,-2.8) M3(-1.6,-2.8) M7(1.6,-2.8) M8(2.4,-2.8) M9(3.2,-2.8) N1(-3.2,-3.6) N2(-2.4,-3.6) N3(-1.6,-3.6) N7(1.6,-3.6) N8(2.4,-3.6) N9(3.2,-3.6) P1(-3.2,-4.4) P2(-2.4,-4.4) P3(-1.6,-4.4) P7(1.6,-4.4) P8(2.4,-4.4) P9(3.2,-4.4) R1(-3.2,-5.2) R2(-2.4,-5.2) R3(-1.6,-5.2) R7(1.6,-5.2) R8(2.4,-5.2) R9(3.2,-5.2) T1(-3.2,-6) T2(-2.4,-6) T3(-1.6,-6) T7(1.6,-6) T8(2.4,-6) T9(3.2,-6)
BGA100_1MM
  round 0.508 smd: A1(-4.503,8.006) A2(-3.503,8.006) A9(3.503,8.006) A10(4.503,8.006) B1(-4.503,7.005) B10(4.503,7.005) D2(-3.503,5.004) D3(-2.502,5.004) D4(-1.501,5.004) D5(-0.5,5.004) D6(0.5,5.004) D7(1.501,5.004) D8(2.502,5.004) D9(3.503,5.004) E2(-3.503,4.003) E3(-2.502,4.003) E4(-1.501,4.003) E5(-0.5,4.003) E6(0.5,4.003) E7(1.501,4.003) E8(2.502,4.003) E9(3.503,4.003) F2(-3.503,3.002) F3(-2.502,3.002) F4(-1.501,3.002) F5(-0.5,3.002) F6(0.5,3.002) F7(1.501,3.002) F8(2.502,3.002) F9(3.503,3.002) G2(-3.503,2.002) G3(-2.502,2.002) G4(-1.501,2.002) G5(-0.5,2.002) G6(0.5,2.002) G7(1.501,2.002) G8(2.502,2.002) G9(3.503,2.002) H2(-3.503,1.001) H3(-2.502,1.001) H4(-1.501,1.001) H5(-0.5,1.001) H6(0.5,1.001) H7(1.501,1.001) H8(2.502,1.001) H9(3.503,1.001) J2(-3.503,0) J3(-2.502,0) J4(-1.501,0) J5(-0.5,0) J6(0.5,0) J7(1.501,0) J8(2.502,0) J9(3.503,0) K2(-3.503,-1.001) K3(-2.502,-1.001) K4(-1.501,-1.001) K5(-0.5,-1.001) K6(0.5,-1.001) K7(1.501,-1.001) K8(2.502,-1.001) K9(3.503,-1.001) L2(-3.503,-2.002) L3(-2.502,-2.002) L4(-1.501,-2.002) L5(-0.5,-2.002) L6(0.5,-2.002) L7(1.501,-2.002) L8(2.502,-2.002) L9(3.503,-2.002) M2(-3.503,-3.002) M3(-2.502,-3.002) M4(-1.501,-3.002) M5(-0.5,-3.002) M6(0.5,-3.002) M7(1.501,-3.002) M8(2.502,-3.002) M9(3.503,-3.002) N2(-3.503,-4.003) N3(-2.502,-4.003) N4(-1.501,-4.003) N5(-0.5,-4.003) N6(0.5,-4.003) N7(1.501,-4.003) N8(2.502,-4.003) N9(3.503,-4.003) P2(-3.503,-5.004) P3(-2.502,-5.004) P4(-1.501,-5.004) P5(-0.5,-5.004) P6(0.5,-5.004) P7(1.501,-5.004) P8(2.502,-5.004) P9(3.503,-5.004) T1(-4.503,-7.005) T10(4.503,-7.005) U1(-4.503,-8.006) U2(-3.503,-8.006) U9(3.503,-8.006) U10(4.503,-8.006)
C402-25
  round 0.635 smd: 1(-0.508,0) 2(0.508,0)
C402-25RD
  round 0.635 smd: 1(-0.508,0) 2(0.508,0)
C603-35X45
  oval 0.889x1.143 smd: 1(-0.762,0) 2(0.762,0)
C805-35X60
  oval 0.889x1.524 smd: 1(-0.965,0) 2(0.965,0)
C1206-40X70
  oval 1.016x1.778 smd: 1(-1.524,0) 2(1.524,0)
C1210-70X102
  rect 1.778x3.048 smd: 1(-1.803,0) 2(1.803,0)
CAP300X630UP
  rect 2.032x2.032 hole 1.049: 1(-7.62,0)
  round 2.032 hole 1.049: 2(0,0)
CAP-FK-D8-65X117
  rect 1.651x2.972 smd: 1(0,2.261) 2(0,-2.261)
CAP-VS-F-8383
  rect 1.27x3.81 smd: 1(0,3.099) 2(0,-3.099)
CHOKE4-AE2002
  rect 1.27x0.762 smd: 1(-2.349,0.699) 2(-2.349,-0.699) 3(2.349,-0.699) 4(2.349,0.699)
COIL-XAL40
  rect 0.914x3.708 smd: 1(-1.194,0) 2(1.194,0)
CON-2214BR-10G
  rect 1.524x1.524 hole 1.016: 1(0,0)
  round 1.524 hole 1.016: 2(0,7.62) 3(-2.54,0) 4(-2.54,7.62) 5(-5.08,0) 6(-5.08,7.62) 7(-7.62,0) 8(-7.62,7.62) 9(-10.16,0) 10(-10.16,7.62)
CON-1932258
  round 1.118 hole 0.711: 1(-3.5,-0.75) 2(-1,-0.75) 3(1,-0.75) 4(3.5,-0.75) 5(4,0.75) 6(2,0.75) 7(0,0.75) 8(-2,0.75) 9(-4,0.75)
  round 2.921 hole 2.311: G1(-6.57,-2.75) G2(6.57,-2.75)
CON_D4S10E
  round 1.524 hole 0.889: 1(-1.001,1.001) 2(-1.001,-1.001) 3(1.001,-1.001) 4(1.001,1.001)
  oval 2.083x2.794 hole 1.6: SH1(-2.502,2.883) SH2(-2.502,-2.883) SH3(2.502,-2.883) SH4(2.502,2.883)
CONN4-MSTBA
  rect 2.54x2.54 hole 1.397: 1(0,0)
  round 2.54 hole 1.397: 2(-5.08,0) 3(-10.16,0) 4(-15.24,0)
CONN-1725711
  round 2.032 hole 1.092: 1(0,0) 2(2.54,0) 3(5.08,0) 4(7.62,0) 5(10.16,0) 6(12.7,0) 7(15.24,0) 8(17.78,0)
CONN-ST-FAKRA
  round 2.032 hole 1.295: 1(0,0)
  round 2.286 hole 1.473: 2(-2.54,2.54) 3(2.54,2.54) 4(-2.54,-2.54) 5(2.54,-2.54)
DCK-5
  rect 0.46x0.66 smd: 1(-0.65,-0.991) 2(0,-0.991) 3(0.65,-0.991) 4(0.65,0.991) 5(-0.65,0.991)
DCU8-10X50
  oval 0.254x1.27 smd: 1(-0.747,-1.499) 2(-0.249,-1.499) 3(0.249,-1.499) 4(0.747,-1.499) 5(0.747,1.499) 6(0.249,1.499) 7(-0.249,1.499) 8(-0.747,1.499)
DDA8-PAD
  oval 0.635x1.905 smd: 1(-1.905,-2.794) 2(-0.635,-2.794) 3(0.635,-2.794) 4(1.905,-2.794) 5(1.905,2.794) 6(0.635,2.794) 7(-0.635,2.794) 8(-1.905,2.794)
  rect 3.099x2.286 smd: 9(0,0)
DGK8-14X70
  oval 0.356x1.778 smd: 1(-0.975,-2.225) 2(-0.325,-2.225) 3(0.325,-2.225) 4(0.975,-2.225) 5(0.975,2.223) 6(0.325,2.223) 7(-0.325,2.223) 8(-0.975,2.223)
DGS10-11X60
  oval 0.279x1.524 smd: 1(-1.001,-2.286) 2(-0.5,-2.286) 3(0,-2.286) 4(0.5,-2.286) 5(1.001,-2.286) 6(1.001,2.286) 7(0.5,2.286) 8(0,2.286) 9(-0.5,2.286) 10(-1.001,2.286)
DI-0805-6
  rect 0.305x0.813 smd: 1(-0.648,-0.699) 2(0,-0.699) 3(0.648,-0.699) 4(0.648,0.699) 5(0,0.699) 6(-0.648,0.699)
DIODE-POWERDI5
  rect 1.143x1.143 smd: ANODE1(-2.87,0.914) ANODE2(-2.87,-0.914)
  rect 4.877x3.353 smd: CATHODE(0.991,0)
DKQ56
  rect 0.406x2.045 smd: 1(-8.572,-4.669) 2(-7.938,-4.669) 3(-7.303,-4.669) 4(-6.668,-4.669) 5(-6.032,-4.669) 6(-5.397,-4.669) 7(-4.763,-4.669) 8(-4.128,-4.669) 9(-3.493,-4.669) 10(-2.857,-4.669) 11(-2.223,-4.669) 12(-1.587,-4.669) 13(-0.953,-4.669) 14(-0.318,-4.669) 15(0.318,-4.669) 16(0.953,-4.669) 17(1.587,-4.669) 18(2.223,-4.669) 19(2.857,-4.669) 20(3.493,-4.669) 21(4.128,-4.669) 22(4.763,-4.669) 23(5.397,-4.669) 24(6.032,-4.669) 25(6.668,-4.669) 26(7.303,-4.669) 27(7.938,-4.669) 28(8.572,-4.669) 29(8.572,4.669) 30(7.938,4.669) 31(7.303,4.669) 32(6.668,4.669) 33(6.032,4.669) 34(5.397,4.669) 35(4.763,4.669) 36(4.128,4.669) 37(3.493,4.669) 38(2.857,4.669) 39(2.223,4.669) 40(1.587,4.669) 41(0.953,4.669) 42(0.318,4.669) 43(-0.318,4.669) 44(-0.953,4.669) 45(-1.587,4.669) 46(-2.223,4.669) 47(-2.857,4.669) 48(-3.493,4.669) 49(-4.128,4.669) 50(-4.763,4.669) 51(-5.397,4.669) 52(-6.032,4.669) 53(-6.668,4.669) 54(-7.303,4.669) 55(-7.938,4.669) 56(-8.572,4.669)
DPY
  rect 0.61x0.508 smd: 1(-0.495,0) 2(0.495,0)
DPY-RDPADS
  oval 0.61x0.508 smd: 1(-0.495,0) 2(0.495,0)
DQA-PSON10
  rect 0.305x0.762 smd: 1(-1,-0.487) 2(-0.5,-0.487) 4(0.5,-0.487) 5(1,-0.487) 6(1,0.487) 7(0.5,0.487) 9(-0.5,0.487) 10(-1,0.487)
  rect 0.406x0.762 smd: 3(0,-0.487) 8(0,0.487)
DRB8-14X33
  rect 0.356x0.851 smd: 1(-0.975,-1.473) 2(-0.325,-1.473) 3(0.325,-1.473) 4(0.975,-1.473) 5(0.975,1.473) 6(0.325,1.473) 7(-0.325,1.473) 8(-0.975,1.473)
  custom 0.406x0.406 smd: 9(0,0)
DRC10-11X33
  rect 0.305x0.762 smd: 1(-1.001,-1.473) 2(-0.5,-1.473) 3(0,-1.473) 4(0.5,-1.473) 5(1.001,-1.473) 6(1.001,1.473) 7(0.5,1.473) 8(0,1.473) 9(-0.5,1.473) 10(-1.001,1.473)
  custom 0.406x0.406 smd: 11(0,0)
DRL5-12X40
  rect 0.305x1.016 smd: 1(-0.5,-0.813) 2(0,-0.813) 3(0.5,-0.813) 4(0.5,0.813) 5(-0.5,0.813)
DSG8-11X20
  rect 0.279x0.508 smd: 1(-0.75,-0.965) 2(-0.25,-0.965) 3(0.25,-0.965) 4(0.75,-0.965) 5(0.75,0.965) 6(0.25,0.965) 7(-0.25,0.965) 8(-0.75,0.965)
  rect 1.6x0.889 smd: 9(0,0)
EMI-36X15-DLW21
  rect 0.914x0.381 smd: 1(-0.838,0.406) 2(0.838,0.406) 3(0.838,-0.406) 4(-0.838,-0.406)
EMI-36X15-DLW21-RDPADS
  oval 0.914x0.381 smd: 1(-0.838,0.406) 2(0.838,0.406) 3(0.838,-0.406) 4(-0.838,-0.406)
EMI-NFM21P
  rect 0.889x0.813 smd: 1(-1.118,0) 3(1.118,0)
  rect 0.508x2.007 smd: 2(0,0)
ESD402
  rect 0.889x0.711 smd: 1(-0.635,0) 2(0.635,0)
FH12-40-SH
  rect 1.346x0.3 smd: 1(0,9.754) 2(0,9.253) 3(0,8.753) 4(0,8.252) 5(0,7.752) 6(0,7.254) 7(0,6.754) 8(0,6.253) 9(0,5.753) 10(0,5.253) 11(0,4.755) 12(0,4.255) 13(0,3.754) 14(0,3.254) 15(0,2.753) 16(0,2.256) 17(0,1.755) 18(0,1.255) 19(0,0.754) 20(0,0.254) 21(0,-0.246) 22(0,-0.747) 23(0,-1.247) 24(0,-1.748) 25(0,-2.248) 26(0,-2.748) 27(0,-3.249) 28(0,-3.749) 29(0,-4.249) 30(0,-4.75) 31(0,-5.25) 32(0,-5.751) 33(0,-6.251) 34(0,-6.751) 35(0,-7.252) 36(0,-7.752) 37(0,-8.252) 38(0,-8.753) 39(0,-9.253) 40(0,-9.754)
  rect 2.718x2.311 smd: 41(-3.251,11.659) 42(-3.251,-11.659)
FX8-120P-SV1
  round 0.508 hole 1.092 unplated: (-20.091,-1.499)
  round 0.254 hole 0.711 unplated: (20.091,-1.499)
  rect 0.356x1.524 smd: 1(-17.694,-2.7) 2(-17.094,-2.7) 3(-16.495,-2.7) 4(-15.895,-2.7) 5(-15.296,-2.7) 6(-14.696,-2.7) 7(-14.097,-2.7) 8(-13.498,-2.7) 9(-12.898,-2.7) 10(-12.299,-2.7) 11(-11.699,-2.7) 12(-11.1,-2.7) 13(-10.5,-2.7) 14(-9.901,-2.7) 15(-9.301,-2.7) 16(-8.702,-2.7) 17(-8.103,-2.7) 18(-7.503,-2.7) 19(-6.904,-2.7) 20(-6.304,-2.7) 21(-5.69,-2.7) 22(-5.095,-2.7) 23(-4.495,-2.7) 24(-3.895,-2.7) 25(-3.295,-2.7) 26(-2.695,-2.7) 27(-2.095,-2.7) 28(-1.495,-2.7) 29(-0.895,-2.7) 30(-0.295,-2.7) 31(0.305,-2.7) 32(0.905,-2.7) 33(1.505,-2.7) 34(2.105,-2.7) 35(2.705,-2.7) 36(3.305,-2.7) 37(3.907,-2.7) 38(4.506,-2.7) 39(5.105,-2.7) 40(5.705,-2.7) 41(6.304,-2.7) 42(6.904,-2.7) 43(7.503,-2.7) 44(8.103,-2.7) 45(8.702,-2.7) 46(9.301,-2.7) 47(9.901,-2.7) 48(10.5,-2.7) 49(11.1,-2.7) 50(11.699,-2.7) 51(12.299,-2.7) 52(12.898,-2.7) 53(13.498,-2.7) 54(14.097,-2.7) 55(14.696,-2.7) 56(15.296,-2.7) 57(15.895,-2.7) 58(16.495,-2.7) 59(17.094,-2.7) 60(17.694,-2.7) 61(17.694,2.7) 62(17.094,2.7) 63(16.495,2.7) 64(15.895,2.7) 65(15.296,2.7) 66(14.696,2.7) 67(14.097,2.7) 68(13.498,2.7) 69(12.898,2.7) 70(12.299,2.7) 71(11.699,2.7) 72(11.1,2.7) 73(10.5,2.7) 74(9.901,2.7) 75(9.301,2.7) 76(8.702,2.7) 77(8.103,2.7) 78(7.503,2.7) 79(6.904,2.7) 80(6.304,2.7) 81(5.705,2.7) 82(5.105,2.7) 83(4.506,2.7) 84(3.907,2.7) 85(3.305,2.7) 86(2.705,2.7) 87(2.105,2.7) 88(1.505,2.7) 89(0.905,2.7) 90(0.305,2.7) 91(-0.295,2.7) 92(-0.895,2.7) 93(-1.495,2.7) 94(-2.094,2.7) 95(-2.694,2.7) 96(-3.294,2.7) 97(-3.894,2.7) 98(-4.494,2.7) 99(-5.094,2.7) 100(-5.694,2.7) 101(-6.304,2.7) 102(-6.904,2.7) 103(-7.503,2.7) 104(-8.103,2.7) 105(-8.702,2.7) 106(-9.301,2.7) 107(-9.901,2.7) 108(-10.5,2.7) 109(-11.1,2.7) 110(-11.699,2.7) 111(-12.299,2.7) 112(-12.898,2.7) 113(-13.498,2.7) 114(-14.097,2.7) 115(-14.696,2.7) 116(-15.296,2.7) 117(-15.895,2.7) 118(-16.495,2.7) 119(-17.094,2.7) 120(-17.694,2.7)
HDMI-SMT-W-FLANGE-RDPADS
  oval 0.279x1.905 smd: 1(4.75,0) 2(4.249,0) 3(3.749,0) 4(3.249,0) 5(2.748,0) 6(2.248,0) 7(1.748,0) 8(1.247,0) 9(0.747,0) 10(0.246,0) 11(-0.254,0) 12(-0.754,0) 13(-1.255,0) 14(-1.755,0) 15(-2.256,0) 16(-2.756,0) 17(-3.256,0) 18(-3.757,0) 19(-4.257,0)
  round 2.032 hole 1.295: MTG1(-7.239,-1.001) MTG2(7.239,-1.001) MTG3(-7.849,-5.9) MTG4(7.849,-5.9)
HPH1-3-4025
  round 1.016 hole 0.635: 1(0,0) 2(1.27,0) 3(2.54,0)
IC8-CP-USON
  rect 0.254x1.016 smd: 1(-0.75,-1.27) 2(-0.25,-1.27) 3(0.25,-1.27) 4(0.75,-1.27) 5(0.75,1.27) 6(0.25,1.27) 7(-0.25,1.27) 8(-0.75,1.27)
  rect 1.27x0.254 smd: 9(0,0)
IND2-65X90-IHLP1616
  rect 1.651x2.286 smd: 1(-1.651,0) 2(1.651,0)
IND2-7030D
  rect 2.032x3.81 smd: 1(-2.921,0) 2(2.921,0)
IND2-ATCA-06
  round 2.286 hole 1.219: 1(-7.493,0) 2(7.493,0)
IND2-FDSD0420
  rect 1.524x2.413 smd: 1(-1.651,0) 2(1.651,0)
IND402-14X26
  rect 0.356x0.66 smd: 1(-0.406,0) 2(0.406,0)
IND603-AISC-25X40
  rect 0.635x1.016 smd: 1(-0.635,0) 2(0.635,0)
IND0805-40X70
  rect 1.016x1.778 smd: 1(-0.889,0) 2(0.889,0)
IND1515-40X100
  rect 1.016x2.54 smd: 1(-1.143,0) 2(1.143,0)
IND2520-40X80
  rect 1.016x2.032 smd: 1(-1.118,0) 2(1.118,0)
IND-DFEG10040
  rect 2.997x3.429 smd: 1(-4.445,0) 2(4.445,0)
IND-IHLP2020
  rect 1.778x2.794 smd: 1(-2.413,0) 2(2.413,0)
IND-IHLP5050
  rect 2.921x5.385 smd: 1(-5.461,0) 2(5.461,0)
IND-IHLP-COMBO
  custom 0.724x0.724 smd: 1(-3.607,0) 2(3.607,0)
IND-MSS7341
  rect 2.54x7.112 smd: 1(-2.286,0) 2(2.286,0)
J6ENTRY_DRA71X_ZDN_V4
  round 0.3 smd: A1(-7.8,7.8) A2(-7.15,7.8) A3(-6.5,7.8) A4(-5.85,7.8) A5(-5.2,7.8) A6(-4.55,7.8) A7(-3.9,7.8) A8(-3.25,7.8) A9(-2.6,7.8) A10(-1.95,7.8) A11(-1.3,7.8) A12(-0.65,7.8) A13(0,7.8) A14(0.65,7.8) A15(1.3,7.8) A16(1.95,7.8) A17(2.6,7.8) A18(3.25,7.8) A19(3.9,7.8) A20(4.55,7.8) A21(5.2,7.8) A22(5.85,7.8) A23(6.5,7.8) A24(7.15,7.8) A25(7.8,7.8) AA1(-7.8,-5.2) AA2(-7.15,-5.2) AA3(-6.5,-5.2) AA4(-5.852,-5.202) AA5(-5.202,-5.202) AA6(-4.552,-5.202) AA7(-3.9,-5.2) AA8(-3.251,-5.202) AA9(-2.6,-5.2) AA10(-1.95,-5.2) AA11(-1.3,-5.202) AA12(-0.65,-5.2) AA13(0,-5.2) AA15(1.3,-5.2) AA16(1.95,-5.2) AA18(3.25,-5.2) AA19(3.9,-5.2) AA20(4.552,-5.202) AA21(5.202,-5.202) AA23(6.502,-5.202) AA24(7.15,-5.2) AA25(7.8,-5.2) AB1(-7.8,-5.85) AB2(-7.153,-5.852) AB6(-4.55,-5.85) AB7(-3.9,-5.85) AB8(-3.251,-5.852) AB9(-2.6,-5.85) AB10(-1.95,-5.85) AB11(-1.3,-5.852) AB12(-0.65,-5.852) AB15(1.3,-5.85) AB16(1.95,-5.85) AB18(3.25,-5.85) AB19(3.9,-5.85) AB23(6.502,-5.852) AB24(7.15,-5.85) AB25(7.8,-5.85) AC1(-7.8,-6.5) AC2(-7.15,-6.5) AC3(-6.5,-6.5) AC4(-5.852,-6.502) AC5(-5.2,-6.5) AC6(-4.55,-6.5) AC8(-3.251,-6.502) AC10(-1.95,-6.5) AC11(-1.3,-6.502) AC13(0,-6.502) AC15(1.3,-6.5) AC16(1.95,-6.5) AC18(3.25,-6.5) AC19(3.901,-6.502) AC20(4.55,-6.5) AC21(5.2,-6.5) AC22(5.852,-6.502) AC23(6.5,-6.5) AC24(7.15,-6.5) AC25(7.8,-6.5) AD1(-7.8,-7.15) AD2(-7.153,-7.153) AD3(-6.5,-7.15) AD4(-5.85,-7.15) AD6(-4.552,-7.153) AD7(-3.9,-7.15) AD9(-2.601,-7.153) AD10(-1.95,-7.15) AD12(-0.65,-7.153) AD13(0,-7.15) AD15(1.3,-7.15) AD16(1.95,-7.15) AD17(2.6,-7.15) AD18(3.25,-7.15) AD19(3.9,-7.15) AD20(4.55,-7.15) AD21(5.2,-7.15) AD22(5.85,-7.15) AD23(6.5,-7.15) AD24(7.15,-7.15) AD25(7.8,-7.15) AE1(-7.8,-7.8) AE2(-7.15,-7.8) AE3(-6.5,-7.8) AE5(-5.2,-7.8) AE6(-4.55,-7.8) AE8(-3.25,-7.8) AE9(-2.6,-7.8) AE11(-1.3,-7.8) AE12(-0.65,-7.8) AE14(0.65,-7.8) AE15(1.3,-7.8) AE16(1.95,-7.8) AE17(2.6,-7.8) AE18(3.25,-7.8) AE19(3.9,-7.8) AE20(4.55,-7.8) AE21(5.2,-7.8) AE22(5.85,-7.8) AE23(6.5,-7.8) AE24(7.15,-7.8) AE25(7.8,-7.8) B1(-7.8,7.15) B2(-7.15,7.15) B3(-6.5,7.15) B4(-5.85,7.15) B5(-5.2,7.15) B6(-4.55,7.15) B7(-3.9,7.15) B8(-3.25,7.15) B9(-2.6,7.15) B10(-1.95,7.15) B11(-1.3,7.15) B12(-0.65,7.15) B13(0,7.15) B14(0.65,7.15) B15(1.3,7.15) B16(1.95,7.15) B17(2.6,7.15) B18(3.25,7.15) B19(3.9,7.15) B20(4.55,7.15) B21(5.2,7.15) B22(5.85,7.15) B23(6.5,7.15) B24(7.15,7.15) B25(7.8,7.15) C1(-7.8,6.5) C2(-7.15,6.5) C3(-6.5,6.5) C4(-5.852,6.502) C5(-5.2,6.5) C6(-4.55,6.5) C7(-3.901,6.502) C8(-3.25,6.5) C10(-1.95,6.5) C11(-1.3,6.5) C13(0,6.5) C14(0.65,6.5) C16(1.95,6.5) C17(2.6,6.5) C19(3.9,6.5) C20(4.55,6.5) C21(5.202,6.502) C22(5.852,6.502) C23(6.5,6.5) C24(7.15,6.5) C25(7.8,6.5) D1(-7.8,5.85) D2(-7.15,5.85) D3(-6.502,5.852) D6(-4.55,5.85) D7(-3.9,5.85) D8(-3.25,5.85) D10(-1.95,5.85) D11(-1.3,5.85) D13(0,5.85) D14(0.65,5.85) D16(1.95,5.85) D17(2.6,5.85) D19(3.9,5.85) D20(4.55,5.85) D23(6.502,5.852) D24(7.15,5.85) D25(7.8,5.85) E1(-7.8,5.2) E2(-7.15,5.2) E7(-3.9,5.2) E8(-3.25,5.2) E10(-1.95,5.2) E11(-1.3,5.2) E13(0,5.2) E14(0.65,5.2) E16(1.95,5.2) E17(2.6,5.2) E19(3.9,5.2) E20(4.552,5.202) E24(7.15,5.2) E25(7.8,5.2) F1(-7.8,4.55) F2(-7.15,4.55) F3(-6.5,4.55) F6(-4.55,4.55) F7(-3.9,4.55) F8(-3.25,4.55) F10(-1.95,4.55) F11(-1.3,4.552) F13(0,4.55) F14(0.65,4.55) F16(1.95,4.55) F17(2.6,4.55) F19(3.9,4.55) F20(4.55,4.55) F23(6.5,4.55) F24(7.15,4.55) F25(7.8,4.55) G1(-7.8,3.9) G2(-7.15,3.9) G3(-6.5,3.9) G4(-5.85,3.9) G5(-5.2,3.9) G6(-4.55,3.9) G7(-3.901,3.901) G8(-3.25,3.9) G9(-2.601,3.901) G10(-1.95,3.9) G11(-1.3,3.9) G12(-0.65,3.901) G13(0,3.9) G14(0.65,3.9) G15(1.3,3.901) G16(1.95,3.9) G17(2.6,3.9) G18(3.251,3.901) G19(3.901,3.901) G20(4.55,3.9) G21(5.2,3.9) G22(5.85,3.9) G23(6.502,3.901) G24(7.15,3.9) G25(7.8,3.9) H1(-7.8,3.25) H2(-7.15,3.25) H3(-6.502,3.251) H4(-5.852,3.251) H5(-5.202,3.251) H6(-4.552,3.251) H7(-3.901,3.251) H8(-3.25,3.25) H9(-2.6,3.25) H10(-1.95,3.25) H11(-1.3,3.25) H12(-0.65,3.25) H13(0,3.25) H14(0.65,3.25) H15(1.3,3.25) H16(1.95,3.25) H17(2.6,3.25) H18(3.25,3.25) H19(3.9,3.25) H20(4.55,3.25) H21(5.2,3.25) H22(5.85,3.25) H23(6.5,3.25) H24(7.15,3.25) H25(7.8,3.25) J1(-7.8,2.6) J2(-7.15,2.6) J7(-3.9,2.6) J8(-3.25,2.6) J9(-2.6,2.6) J10(-1.95,2.6) J11(-1.3,2.6) J12(-0.65,2.6) J13(0,2.6) J14(0.65,2.6) J15(1.3,2.6) J16(1.95,2.6) J17(2.6,2.6) J18(3.25,2.6) J19(3.901,2.601) J20(4.552,2.601) J24(7.15,2.6) J25(7.8,2.6) K1(-7.8,1.95) K2(-7.15,1.95) K3(-6.5,1.95) K4(-5.85,1.95) K5(-5.2,1.95) K6(-4.55,1.95) K7(-3.9,1.95) K8(-3.25,1.95) K9(-2.6,1.95) K10(-1.951,1.951) K11(-1.3,1.95) K12(-0.65,1.95) K13(0,1.951) K14(0.65,1.95) K15(1.3,1.95) K16(1.951,1.951) K17(2.6,1.95) K18(3.25,1.95) K19(3.9,1.95) K20(4.55,1.95) K21(5.2,1.95) K22(5.85,1.95) K23(6.5,1.95) K24(7.15,1.95) K25(7.8,1.95) L1(-7.8,1.3) L2(-7.15,1.3) L3(-6.502,1.3) L4(-5.852,1.3) L5(-5.202,1.3) L6(-4.552,1.3) L7(-3.901,1.3) L8(-3.25,1.3) L9(-2.6,1.3) L10(-1.951,1.3) L11(-1.3,1.3) L12(-0.65,1.3) L13(0,1.3) L14(0.65,1.3) L15(1.3,1.3) L16(1.951,1.3) L17(2.6,1.3) L18(3.25,1.3) L19(3.9,1.3) L20(4.55,1.3) L21(5.2,1.3) L22(5.85,1.3) L23(6.5,1.3) L24(7.15,1.3) L25(7.8,1.3) M1(-7.8,0.65) M2(-7.15,0.65) M7(-3.9,0.65) M8(-3.25,0.65) M9(-2.6,0.65) M10(-1.95,0.65) M11(-1.3,0.65) M12(-0.65,0.65) M13(0,0.65) M14(0.65,0.65) M15(1.3,0.65) M16(1.95,0.65) M17(2.6,0.65) M18(3.25,0.65) M19(3.901,0.65) M20(4.552,0.65) M24(7.15,0.65) M25(7.8,0.65) N1(-7.8,0) N2(-7.15,0) N3(-6.5,0) N4(-5.85,0) N5(-5.2,0) N6(-4.55,0) N7(-3.9,0) N8(-3.25,0) N9(-2.6,0) N10(-1.95,0) N11(-1.3,0) N12(-0.65,0) N13(0,0) N14(0.65,0) N15(1.3,0) N16(1.95,0) N17(2.6,0) N18(3.25,0) N19(3.9,0) N20(4.55,0) N21(5.2,0) N22(5.85,0) N23(6.5,0) N24(7.15,0) N25(7.8,0) P1(-7.8,-0.65) P2(-7.15,-0.65) P3(-6.502,-0.65) P4(-5.852,-0.65) P5(-5.202,-0.65) P7(-3.901,-0.65) P8(-3.25,-0.65) P9(-2.6,-0.65) P10(-1.95,-0.65) P11(-1.3,-0.65) P12(-0.65,-0.65) P13(0,-0.65) P14(0.65,-0.65) P15(1.3,-0.65) P16(1.95,-0.65) P17(2.6,-0.65) P18(3.25,-0.65) P19(3.9,-0.65) P20(4.55,-0.65) P21(5.2,-0.65) P22(5.85,-0.65) P23(6.5,-0.65) P24(7.15,-0.65) P25(7.8,-0.65) R1(-7.8,-1.3) R2(-7.15,-1.3) R7(-3.9,-1.3) R8(-3.25,-1.3) R9(-2.6,-1.3) R10(-1.951,-1.3) R11(-1.3,-1.3) R12(-0.65,-1.3) R13(0,-1.3) R14(0.65,-1.3) R15(1.3,-1.3) R16(1.951,-1.3) R17(2.6,-1.3) R18(3.25,-1.3) R19(3.901,-1.3) R20(4.552,-1.3) R24(7.15,-1.3) R25(7.8,-1.3) T1(-7.8,-1.95) T2(-7.15,-1.95) T3(-6.5,-1.95) T4(-5.85,-1.95) T5(-5.2,-1.95) T6(-4.55,-1.95) T7(-3.9,-1.95) T8(-3.25,-1.95) T9(-2.6,-1.95) T10(-1.951,-1.951) T11(-1.3,-1.95) T12(-0.65,-1.95) T13(0,-1.951) T14(0.65,-1.95) T15(1.3,-1.95) T16(1.951,-1.951) T17(2.6,-1.95) T18(3.25,-1.95) T19(3.9,-1.95) T20(4.55,-1.95) T21(5.2,-1.95) T22(5.85,-1.95) T23(6.5,-1.95) T24(7.15,-1.95) T25(7.8,-1.95) U1(-7.8,-2.6) U2(-7.15,-2.6) U3(-6.502,-2.601) U4(-5.852,-2.601) U5(-5.202,-2.601) U6(-4.552,-2.601) U7(-3.901,-2.601) U8(-3.25,-2.6) U9(-2.601,-2.601) U10(-1.95,-2.6) U11(-1.3,-2.6) U12(-0.65,-2.6) U13(0,-2.6) U14(0.65,-2.6) U15(1.3,-2.6) U16(1.95,-2.6) U17(2.6,-2.6) U18(3.25,-2.6) U19(3.9,-2.6) U20(4.55,-2.6) U21(5.2,-2.6) U22(5.85,-2.6) U23(6.5,-2.6) U24(7.15,-2.6) U25(7.8,-2.6) V1(-7.8,-3.25) V2(-7.15,-3.25) V3(-6.5,-3.25) V4(-5.85,-3.25) V5(-5.2,-3.25) V7(-3.9,-3.25) V8(-3.25,-3.25) V9(-2.6,-3.25) V10(-1.95,-3.25) V11(-1.3,-3.25) V12(-0.65,-3.25) V13(0,-3.25) V14(0.65,-3.25) V15(1.3,-3.25) V16(1.95,-3.25) V17(2.6,-3.25) V18(3.25,-3.25) V19(3.901,-3.251) V20(4.552,-3.251) V24(7.15,-3.25) V25(7.8,-3.25) W1(-7.8,-3.9) W2(-7.15,-3.9) W7(-3.901,-3.901) W8(-3.251,-3.901) W9(-2.601,-3.901) W10(-1.95,-3.9) W11(-1.3,-3.901) W12(-0.65,-3.9) W13(0,-3.9) W14(0.65,-3.901) W15(1.3,-3.9) W16(1.95,-3.9) W17(2.601,-3.901) W18(3.25,-3.9) W19(3.901,-3.901) W20(4.55,-3.9) W21(5.2,-3.9) W22(5.85,-3.9) W23(6.5,-3.9) W24(7.15,-3.9) W25(7.8,-3.9) Y1(-7.8,-4.55) Y2(-7.15,-4.55) Y3(-6.5,-4.55) Y4(-5.85,-4.55) Y5(-5.202,-4.552) Y6(-4.55,-4.55) Y7(-3.9,-4.55) Y8(-3.251,-4.552) Y9(-2.601,-4.552) Y10(-1.95,-4.55) Y11(-1.3,-4.552) Y12(-0.65,-4.55) Y13(0,-4.55) Y14(0.65,-4.552) Y15(1.3,-4.55) Y16(1.95,-4.55) Y17(2.601,-4.552) Y18(3.25,-4.55) Y19(3.9,-4.55) Y20(4.55,-4.55) Y21(5.202,-4.552) Y23(6.5,-4.55) Y24(7.15,-4.55) Y25(7.8,-4.55)
